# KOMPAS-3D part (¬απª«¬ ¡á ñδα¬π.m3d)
File: created 22.07.2016 15:44:20, last saved 22.07.2016 15:55:30.
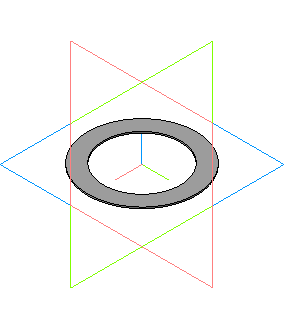
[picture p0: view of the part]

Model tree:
1. Эскиз:1
2. Операция выдавливания:1
     Толщина стенки 2 = 15; Расстояние 1 = 0.5; Расстояние 2 = 96.2519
